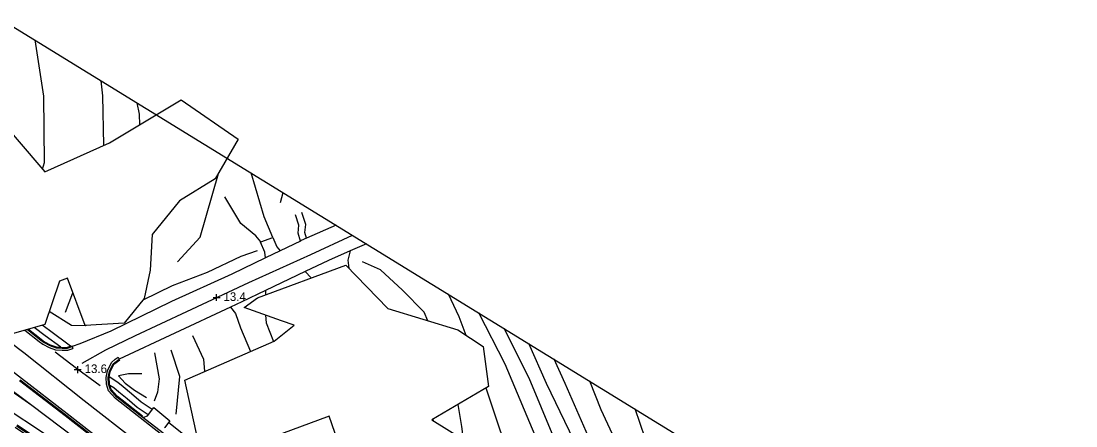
# Model space of a CAD drawing. Extents: x 2316231 to 2323598, y 363169 to 371906.
# Drawn here: x 2319714 to 2320328, y 366614 to 366849 of the extents above; entities that cross this region are included whole.
import ezdxf

# ---------------------------------------------------------------- set-up
doc = ezdxf.new("R2010")
doc.units = 0
for name, color, linetype in [('RD_DTM_BkLn1', 7, 'Continuous'), ('RD_DTM_Holes', 7, 'Continuous'), ('RD_DTM_TinHull', 7, 'Continuous'), ('RD_DTM_Void', 7, 'Continuous'), ('RD_EX_Road', 7, 'Continuous')]:
    doc.layers.add(name, color=color, linetype=linetype)

msp = doc.modelspace()

# ---------------------------------------------------------------- linework, layer by layer
at = {"layer": 'RD_DTM_BkLn1'}
for p, q in [((2319864.673, 366743.751), (2319866.076, 366749.51)), ((2319739.377, 366679.823), (2319743.748, 366691.059)), ((2319805.926, 366642.477), (2319801.025, 366657.724)), ((2319803.956, 366620.615), (2319805.926, 366642.477)), ((2319953.673, 366616.613), (2319953.497, 366617.73))]:
    msp.add_line(p, q, dxfattribs=at)
for points in [[(2319726.088, 366763.061), (2319727.245, 366766.882), (2319726.762, 366805.467), (2319721.75, 366838.185)], [(2319761.837, 366776.969), (2319761.193, 366805.78), (2319760.314, 366814.491)], [(2320181.242, 366310.091), (2320155.019, 366325.446), (2320123.083, 366345.253), (2320086.948, 366368.753), (2320053.703, 366393.27), (2320025.668, 366415.513), (2319990.392, 366443.393), (2319961.2, 366465.398), (2319946.981, 366477.722), (2319911.261, 366503.831), (2319880.301, 366528.217), (2319842.976, 366556.718), (2319811.094, 366581.051), (2319781.152, 366604.205), (2319750.318, 366628.239), (2319715.24, 366656.141), (2319656.149, 366700.693), (2319623.266, 366725.395), (2319586.108, 366754.455), (2319538.084, 366791.417), (2319519.19, 366805.873)], [(2319782.701, 366788.924), (2319782.482, 366795.111), (2319781.169, 366801.678)], [(2319523.713, 366682.618), (2319520.433, 366685.837), (2319519.172, 366689.1), (2319517.268, 366693.885), (2319514.719, 366703.224), (2319509.801, 366721.19), (2319509.444, 366738.902), (2319510.778, 366748.005), (2319512.215, 366755.124), (2319513.544, 366761.73), (2319516.272, 366769.901), (2319519.408, 366772.948), (2319525.134, 366772.605), (2319539.014, 366765.347), (2319584.799, 366730.232), (2319642.331, 366684.582), (2319702.289, 366638.975), (2319719.814, 366625.793)], [(2319804.621, 366709.22), (2319817.878, 366723.421), (2319828.483, 366760.469)], [(2319547.68, 366749.642), (2319580.096, 366724.92), (2319642.581, 366678.596), (2319712.176, 366631.195), (2319719.814, 366625.793)], [(2319545.619, 366731.421), (2319574.97, 366712.367), (2319613.373, 366686.262), (2319654.481, 366658.144), (2319703.709, 366624.907), (2319750.677, 366593.75), (2319802.313, 366557.848)], [(2319749.22, 366650.204), (2319762.889, 366658.055), (2319780.211, 366666.232), (2319810.012, 366680.343), (2319846.258, 366697.117), (2319882.28, 366713.414), (2319906.526, 366724.657)], [(2319851.087, 366715.622), (2319841.485, 366712.246), (2319821.869, 366703.012), (2319801.608, 366695.136), (2319784.568, 366686.866)], [(2319950.448, 366674.916), (2319948.213, 366679.875), (2319935.63, 366692.585), (2319922.832, 366704.573), (2319912.328, 366709.195)], [(2319972.739, 366666.357), (2319968.635, 366677.204), (2319962.459, 366690.292)], [(2319751.404, 366672.115), (2319750.943, 366671.904), (2319742.871, 366672.134), (2319729.989, 366680.319)], [(2319991.889, 366534.267), (2320005.409, 366540.882), (2320022.591, 366550.623), (2320031.181, 366561.403), (2320028.295, 366579.495), (2320015.406, 366602.1), (2319995.315, 366649.604), (2319980.027, 366679.498)], [(2319813.368, 366666.238), (2319819.703, 366652.58), (2319820.447, 366645.3)], [(2320052.403, 366568.141), (2320042.188, 366589.445), (2320032.848, 366610.579), (2320019.411, 366638.298), (2320009.086, 366661.644)], [(2319759.711, 366636.983), (2319745.78, 366647.066), (2319733.444, 366656.67)], [(2319791.227, 366656.286), (2319794.016, 366641.03), (2319792.984, 366633.407), (2319791.162, 366628.135)], [(2319783.887, 366644.086), (2319776.186, 366643.964), (2319770.402, 366642.755), (2319774.259, 366638.657), (2319779.715, 366634.572), (2319786.709, 366630.324)], [(2320067.418, 366588.572), (2320062.862, 366597.995), (2320051.25, 366623.041), (2320044.765, 366639.723)], [(2320013.041, 366558.26), (2320001.404, 366584.765), (2319984.264, 366635.721)], [(2319719.814, 366625.793), (2319753.209, 366600.674), (2319804.394, 366561.812), (2319860.331, 366521.855), (2319869.509, 366514.559), (2319877.211, 366509.7)], [(2319971.103, 366605.804), (2319970.228, 366613.294), (2319967.967, 366626.191)], [(2320083.443, 366591.274), (2320076.921, 366606.567), (2320071.006, 366623.6)]]:
    msp.add_lwpolyline(points, dxfattribs=at)
at = {"layer": 'RD_DTM_Holes'}
for points in [[(2319806.828, 366803.309), (2319840.027, 366780.448), (2319826.686, 366757.358), (2319805.808, 366744.632), (2319789.842, 366725.048), (2319788.697, 366704.347), (2319785.341, 366687.804), (2319773.529, 366673.476), (2319750.828, 366672.08), (2319740.54, 366699.66), (2319735.954, 366697.837), (2319727.417, 366672.765), (2319709.263, 366667.546), (2319675.193, 366696.059), (2319671.085, 366716.364), (2319682.373, 366752.991), (2319664.472, 366769.482), (2319668.928, 366791.548), (2319696.131, 366797.732), (2319727.395, 366761.549), (2319765.101, 366778.43), (2319806.828, 366803.309)], [(2319816.705, 366604.813), (2319808.956, 366640.286), (2319860.9, 366662.949), (2319872.478, 366672.227), (2319865.181, 366674.855), (2319843.511, 366682.669), (2319851.238, 366688.309), (2319902.597, 366707.255), (2319927.169, 366682.038), (2319967.813, 366669.603), (2319982.61, 366659.853), (2319985.694, 366636.557), (2319952.661, 366617.241), (2319980.473, 366599.994)], [(2319897.976, 366604.91), (2319892.871, 366619.295), (2319859.97, 366607.235)]]:
    msp.add_lwpolyline(points, dxfattribs=at)
at = {"layer": 'RD_DTM_TinHull'}
msp.add_lwpolyline([(2318009.783, 367630.234), (2318999.407, 367049.655), (2319281.252, 367000.442), (2319521.217, 366961.394), (2320716.689, 366226.888), (2320934.852, 366280.749), (2321141.465, 366502.562), (2321263.978, 366719.924), (2321282.537, 366948.249), (2321279.947, 367175.232), (2321214.652, 367465.641), (2321221.515, 367818.629), (2321207.427, 368150.673), (2321267.86, 368369.229), (2321400.963, 368599.408), (2321534.916, 368777.939)], dxfattribs=at)
at = {"layer": 'RD_DTM_Void'}
for p, q in [((2319825.43, 366688.404), (2319829.43, 366688.404)), ((2319827.43, 366686.404), (2319827.43, 366690.404)), ((2319744.607, 366646.467), (2319748.607, 366646.467)), ((2319746.607, 366644.467), (2319746.607, 366648.467))]:
    msp.add_line(p, q, dxfattribs=at)
at = {"layer": 'RD_EX_Road'}
for p, q in [((2319897.104, 366730.446), (2319879.822, 366722.871)), ((2319853.2, 366720.706), (2319860.077, 366723.377)), ((2319876.166, 366721.242), (2319864.475, 366715.568)), ((2319914.587, 366719.705), (2319905.104, 366715.475)), ((2319864.475, 366715.568), (2319855.933, 366711.421)), ((2319879.061, 366703.451), (2319855.972, 366692.454)), ((2319879.061, 366703.451), (2319882.423, 366699.813)), ((2319855.972, 366692.454), (2319855.867, 366690.017)), ((2319835.469, 366682.758), (2319770.761, 366652.6)), ((2319742.404, 366660.029), (2319743.262, 366660.298)), ((2319743.412, 366659.821), (2319743.771, 366658.676)), ((2319770.139, 366653.747), (2319770.761, 366652.6))]:
    msp.add_line(p, q, dxfattribs=at)
for points in [[(2319860.077, 366723.377), (2319855.165, 366735.369), (2319847.625, 366760.847)], [(2319853.2, 366720.706), (2319850.201, 366724.25), (2319841.465, 366731.485), (2319832.214, 366746.867)], [(2319876.166, 366721.242), (2319874.822, 366725.797), (2319875.318, 366730.52), (2319873.315, 366736.569)], [(2319879.822, 366722.871), (2319878.85, 366726.165), (2319879.353, 366730.956), (2319877.081, 366737.816)], [(2319860.077, 366723.377), (2319862.442, 366717.808), (2319864.475, 366715.568)], [(2319879.822, 366722.871), (2319876.724, 366721.513), (2319876.166, 366721.242)], [(2319855.933, 366711.421), (2319855.468, 366714.81), (2319852.964, 366720.614), (2319853.2, 366720.706)], [(2319855.933, 366711.421), (2319836.386, 366701.933), (2319801.102, 366686.016), (2319765.809, 366668.815), (2319747.85, 366661.507), (2319743.412, 366659.821)], [(2319905.104, 366715.475), (2319892.558, 366709.878), (2319879.061, 366703.451)], [(2319905.104, 366715.475), (2319903.759, 366710.047), (2319904.3, 366705.506)], [(2319855.972, 366692.454), (2319842.156, 366685.875), (2319835.469, 366682.758)], [(2319835.469, 366682.758), (2319838.33, 366679.157), (2319841.412, 366670.841), (2319847.216, 366656.979)], [(2319855.872, 366678.212), (2319856.283, 366673.714), (2319860.484, 366662.768)], [(2319715.86, 366669.442), (2319724.176, 366662.905), (2319726.323, 366661.187), (2319729.962, 366659.366), (2319733.733, 366657.986), (2319737.569, 366657.704), (2319740.895, 366657.774), (2319743.771, 366658.676)], [(2319717.282, 366669.851), (2319724.922, 366663.845), (2319726.974, 366662.203), (2319730.438, 366660.469), (2319733.988, 366659.171), (2319737.601, 366658.904), (2319740.699, 366658.97), (2319743.412, 366659.821)], [(2319717.874, 366670.021), (2319725.233, 366664.237), (2319727.245, 366662.627), (2319730.637, 366660.929), (2319734.094, 366659.664), (2319736.744, 366659.469)], [(2319736.744, 366659.469), (2319727.547, 366666.184), (2319721.17, 366670.969)], [(2319742.404, 366660.029), (2319730.204, 366669.164), (2319725.956, 366672.345)], [(2319994.61, 366670.538), (2320009.226, 366641.727), (2320029.643, 366592.26), (2320042.037, 366565.68), (2320043.313, 366561.18), (2320043.603, 366557.55), (2320043.006, 366555.419), (2320041.991, 366553.804), (2320041.204, 366553.063), (2320039.023, 366551.433), (2320020.014, 366542.323), (2319985.735, 366526.679), (2319962.417, 366515.181)], [(2319684.529, 366664.122), (2319713.879, 366641.439), (2319740.468, 366620.922), (2319774.911, 366594.086), (2319807.973, 366568.262), (2319844.209, 366540.866), (2319872.638, 366518.353), (2319879.787, 366512.75), (2319888.9, 366506.178), (2319890.359, 366504.581), (2319891.535, 366502.473), (2319891.242, 366500.632), (2319889.886, 366498.553), (2319888.32, 366498.062), (2319886.919, 366497.896), (2319884.626, 366498.67), (2319880.57, 366501.032), (2319864.489, 366510.673), (2319841.116, 366525.405), (2319822.753, 366537.338), (2319798.887, 366553.309), (2319769.123, 366573.417), (2319740.658, 366592.488), (2319710.241, 366612.763)], [(2319736.744, 366659.469), (2319737.614, 366659.405), (2319740.617, 366659.469), (2319742.404, 366660.029)], [(2319932.905, 366503.697), (2319930.418, 366504.11), (2319905.424, 366523.67), (2319881.41, 366541.895), (2319857.421, 366560.376), (2319829.01, 366582.2), (2319795.485, 366608.517), (2319768.539, 366629.596), (2319764.51, 366634.104), (2319763.3, 366638.079), (2319763.163, 366641.883), (2319763.877, 366645.693), (2319766.256, 366650.624), (2319768.416, 366652.581), (2319770.139, 366653.747)], [(2319784.459, 366618.666), (2319769.362, 366630.476), (2319765.581, 366634.706), (2319764.494, 366638.279), (2319764.367, 366641.793), (2319765.027, 366645.315), (2319767.242, 366649.906), (2319770.761, 366652.6)], [(2319764.97, 366642.297), (2319765.507, 366645.158), (2319767.641, 366649.582), (2319771.065, 366652.203)], [(2320120.242, 366588.857), (2320117.965, 366587.864), (2320085.215, 366572.28), (2320076.992, 366569.198), (2320073.591, 366568.311), (2320069.893, 366568.371), (2320066.877, 366569.244), (2320064.26, 366570.475), (2320061.134, 366572.281), (2320058.496, 366575.473), (2320056.429, 366580.294), (2320045.218, 366604.276), (2320030.309, 366638.445), (2320023.914, 366652.534)], [(2319710.963, 366613.844), (2319741.38, 366593.569), (2319769.848, 366574.495), (2319799.612, 366554.388), (2319823.469, 366538.423), (2319841.817, 366526.5), (2319865.17, 366511.781), (2319881.231, 366502.151), (2319885.166, 366499.86), (2319887.057, 366499.222), (2319888.047, 366499.339), (2319889.052, 366499.654), (2319890.002, 366501.11), (2319890.18, 366502.233), (2319889.298, 366503.816), (2319887.992, 366505.251), (2319878.523, 366512.211), (2319871.026, 366518.014), (2319843.435, 366539.821), (2319807.181, 366567.232), (2319774.111, 366593.061), (2319739.671, 366619.894), (2319713.085, 366640.41)], [(2319711.241, 366614.26), (2319741.658, 366593.985), (2319770.127, 366574.91), (2319799.891, 366554.803), (2319823.744, 366538.84), (2319842.087, 366526.921), (2319865.432, 366512.207), (2319881.486, 366502.581), (2319885.374, 366500.318), (2319887.11, 366499.732), (2319887.942, 366499.83), (2319888.732, 366500.077), (2319889.525, 366501.293), (2319889.66, 366502.14), (2319888.889, 366503.522), (2319887.656, 366504.877), (2319878.222, 366511.811), (2319870.718, 366517.62), (2319843.13, 366539.425), (2319806.876, 366566.835), (2319773.804, 366592.666), (2319739.365, 366619.499), (2319712.779, 366640.014)], [(2319765.329, 366637.252), (2319764.991, 366638.362), (2319764.869, 366641.756), (2319764.97, 366642.297)], [(2319789.935, 366623.243), (2319783.548, 366627.577), (2319777.862, 366632.356), (2319773.08, 366636.403), (2319769.85, 366639.009), (2319764.97, 366642.297)], [(2319784.343, 366619.392), (2319769.705, 366630.842), (2319766.027, 366634.957), (2319765.329, 366637.252)], [(2319787.556, 366620.161), (2319781.201, 366624.473), (2319775.357, 366629.386), (2319770.604, 366633.407), (2319767.592, 366635.838), (2319765.329, 366637.252)], [(2319784.459, 366618.666), (2319785.043, 366618.715), (2319787.114, 366619.587), (2319790.822, 366624.392), (2319800.219, 366616.651), (2319799.51, 366615.74)], [(2319796.627, 366609.146), (2319796.225, 366609.461), (2319784.459, 366618.666)], [(2319799.51, 366615.74), (2319797.206, 366612.775), (2319797.154, 366612.655)], [(2319859.395, 366569.627), (2319846.665, 366579.314), (2319824.3, 366596.438), (2319809.34, 366607.85), (2319799.51, 366615.74)]]:
    msp.add_lwpolyline(points, dxfattribs=at)

# ---------------------------------------------------------------- texts
at = {"layer": 'RD_DTM_Void'}
for s, p in [('13.4', (2319831.43, 366686.404)), ('13.6', (2319750.607, 366644.467))]:
    msp.add_text(s, height=5, dxfattribs=at).set_placement(p)

doc.saveas('drawing.dxf')
